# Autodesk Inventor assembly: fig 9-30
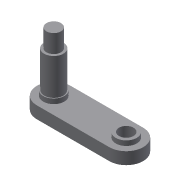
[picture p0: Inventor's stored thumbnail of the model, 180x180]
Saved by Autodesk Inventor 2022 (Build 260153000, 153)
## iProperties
Created: 2002-01
Part Number: fig 9-30
Document SubType Name: Assembly
Designer: ***
Control State: 0
Master: False
Checked Out: False
Shininess: 64.0
Length Units: 11269
Angle Units: 11279
Time Units: 11290
Mass Units: 11283
Length Display Precision: 3
Angle Display Precision: 2
Density: 0.0
Volumn: 0.0
Area: 0.0
PropertySet Name: Model Information
Author: ***
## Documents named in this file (3)
- D:\PROJECTS_2021\Resources\Part Files\c09_Inv_2022_prt\fig 9-34.iam
- D:\PROJECTS_2021\Resources\Part Files\c09_Inv_2022_prt\Part5.ipt
- D:\PROJECTS_2021\Resources\Part Files\c09_Inv_2022_prt\Part6.ipt
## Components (2 placed, 2 different names)
1. Part5:1 — Insert:1
2. Part6:1 — Insert:1
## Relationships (1: Insert 1)
- Insert:1: Part5:1 ↔ Part6:1
